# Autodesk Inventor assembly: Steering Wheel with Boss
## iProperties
Length Units: 11269
Angle Units: 11279
Time Units: 11290
Mass Units: 11283
Shininess: 3
Angle Display Precision: 2
Document Length Units: 11269
Document Angle Units: 11279
Document Time Units: 11290
Document Mass Units: 11283
Document Length Units Precision: 3
Document Angle Units Precision: 2
Compacted: True
Created: 2001-08
Part Number: Steering Wheel with Boss
Document SubType Name: Assembly
Designer: Martin Budgell
Density: 0.0
Volumn: 0.0
Area: 0.0
PropertySet Name: Model Information
Control State: 0
Master: False
Checked Out: False
Author: Martin Budgell
